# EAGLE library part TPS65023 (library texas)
POWER MANAGEMENT IC FOR LI-ION POWERED SYSTEMS Source: http://focus.ti.com/lit/ds/symlink/tps65023.pdf
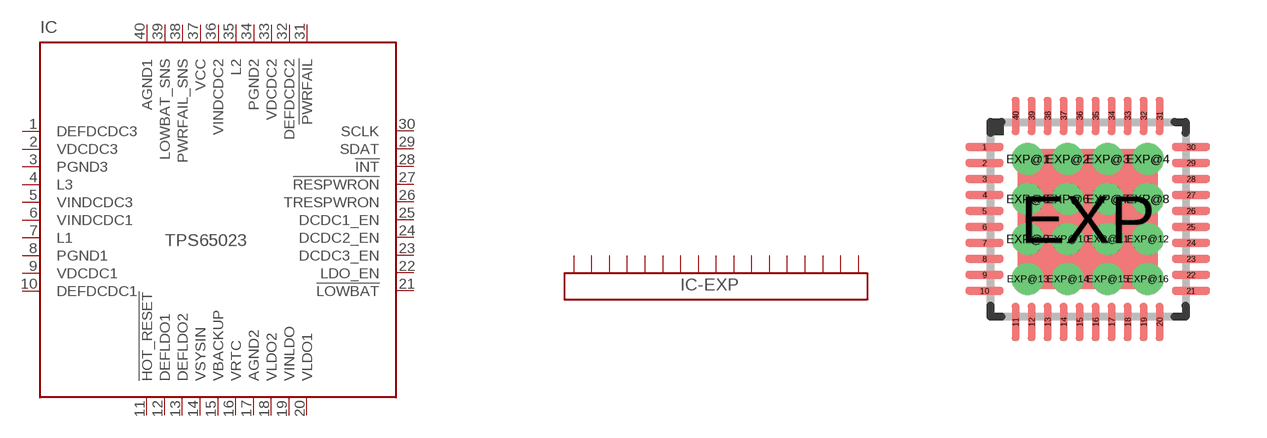
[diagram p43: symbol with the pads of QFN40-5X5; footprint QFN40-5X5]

Designator prefix IC; gates G$1=TPS65023 -EXP=EXP17

## TPS65023 (MPN: TPS65023RSBR; OC_FARNELL: 1652451; OC_NEWARK: 22M1826)  [QFN40-5X5]
1  G$1:DEFDCDC3  in
2  G$1:VDCDC3  in
3  G$1:PGND3  in
4  G$1:L3  pas
5  G$1:VINDCDC3  in
6  G$1:VINDCDC1  in
7  G$1:L1  pas
8  G$1:PGND1  in
9  G$1:VDCDC1  in
10  G$1:DEFDCDC1  in
11  G$1:!HOT_RESET  in
12  G$1:DEFLDO1  in
13  G$1:DEFLDO2  in
14  G$1:VSYSIN  in
15  G$1:VBACKUP  in
16  G$1:VRTC  out
17  G$1:AGND2  in
18  G$1:VLDO2  out
19  G$1:VINLDO  in
20  G$1:VLDO1  out
21  G$1:!LOWBAT  oc
22  G$1:LDO_EN  in
23  G$1:DCDC3_EN  in
24  G$1:DCDC2_EN  in
25  G$1:DCDC1_EN  in
26  G$1:TRESPWRON  in
27  G$1:!RESPWRON  oc
28  G$1:!INT  oc
29  G$1:SDAT
30  G$1:SCLK  in
31  G$1:!PWRFAIL  oc
32  G$1:DEFDCDC2  in
33  G$1:VDCDC2  in
34  G$1:PGND2  in
35  G$1:L2  pas
36  G$1:VINDCDC2  in
37  G$1:VCC  in
38  G$1:PWRFAIL_SNS  in
39  G$1:LOWBAT_SNS  in
40  G$1:AGND1  in
EXP  -EXP:EXP  in
EXP@1  -EXP:EXP16  in
EXP@2  -EXP:EXP16  in
EXP@3  -EXP:EXP16  in
EXP@4  -EXP:EXP16  in
EXP@5  -EXP:EXP16  in
EXP@6  -EXP:EXP16  in
EXP@7  -EXP:EXP16  in
EXP@8  -EXP:EXP16  in
EXP@9  -EXP:EXP16  in
EXP@10  -EXP:EXP16  in
EXP@11  -EXP:EXP16  in
EXP@12  -EXP:EXP16  in
EXP@13  -EXP:EXP16  in
EXP@14  -EXP:EXP16  in
EXP@15  -EXP:EXP16  in
EXP@16  -EXP:EXP16  in

## Footprint QFN40-5X5 (pad centres in mm)
RSB (S-PWQFN-N40) Set restring parameter in design rules to 0, for top, inner, bottom at minimum and %. Source: RSB_TPS65023RSB_Land_Pattern.pdf
smd 0.95 x 0.2: 1 -2.58,1.8; 2 -2.58,1.4; 3 -2.58,1; 4 -2.58,0.6; 5 -2.58,0.2; 6 -2.58,-0.2; 7 -2.58,-0.6; 8 -2.58,-1; 9 -2.58,-1.4; 10 -2.58,-1.8; 21 2.58,-1.8; 22 2.58,-1.4; 23 2.58,-1; 24 2.58,-0.6; 25 2.58,-0.2; 26 2.58,0.2; 27 2.58,0.6; 28 2.58,1; 29 2.58,1.4; 30 2.58,1.8
smd 0.2 x 0.95: 11 -1.8,-2.58; 12 -1.4,-2.58; 13 -1,-2.58; 14 -0.6,-2.58; 15 -0.2,-2.58; 16 0.2,-2.58; 17 0.6,-2.58; 18 1,-2.58; 19 1.4,-2.58; 20 1.8,-2.58; 31 1.8,2.58; 32 1.4,2.58; 33 1,2.58; 34 0.6,2.58; 35 0.2,2.58; 36 -0.2,2.58; 37 -0.6,2.58; 38 -1,2.58; 39 -1.4,2.58; 40 -1.8,2.58
smd 3.5 x 3.5: EXP 0,0
drill 0.3 pad 0.5 round: EXP@1 -1.5,1.5; EXP@2 -0.5,1.5; EXP@3 0.5,1.5; EXP@4 1.5,1.5; EXP@5 -1.5,0.5; EXP@6 -0.5,0.5; EXP@7 0.5,0.5; EXP@8 1.5,0.5; EXP@9 -1.5,-0.5; EXP@10 -0.5,-0.5; EXP@11 0.5,-0.5; EXP@12 1.5,-0.5; EXP@13 -1.5,-1.5; EXP@14 -0.5,-1.5; EXP@15 0.5,-1.5; EXP@16 1.5,-1.5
